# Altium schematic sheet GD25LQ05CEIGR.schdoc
size 127 x 101 mm
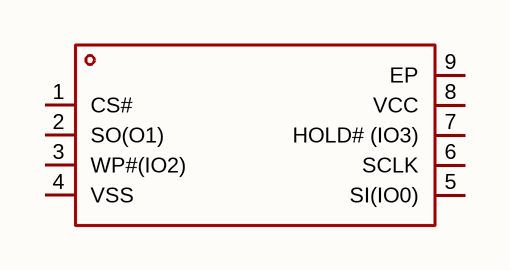
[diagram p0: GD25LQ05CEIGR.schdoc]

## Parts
U?  gd25lq05ceigr  [USON8_L3.0-W2.0-P0.50-BL-EP]  (value not drawn)

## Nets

Not connected (* = marked no-connect by the designer): U? 1(CS#) 2(SO(O1)) 3(WP#(IO2)) 4(VSS) 5(SI(IO0)) 6(SCLK) 7(HOLD#_(IO3)) 8(VCC) 9(EP)

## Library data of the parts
U? = gd25lq05ceigr: 接口类型:SPI;存储容量:512Kbit;时钟频率(fc):104MHz;; Manufacturer: GigaDevice(兆易创新); AddInBom: yes; ModelId: 12a239e5c7384371915ecb51201bf581; ModelName: USON-8_L3.0-W2.0-H0.6-P0.50; ModelTransform: 118.8974,78.74,0,90,0,0,0,0,0; Interface: SPI; Clock Frequency: 104MHz; Voltage - Supply: 1.65V~2.1V; Standby Supply Current: 9uA; Program / Erase Cycles: 100000次; Page Programming Time (Tpp): 700us; Block Erase Time(tBE): 150ms@(32KB); Data Retention - TDR (Year): 20年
